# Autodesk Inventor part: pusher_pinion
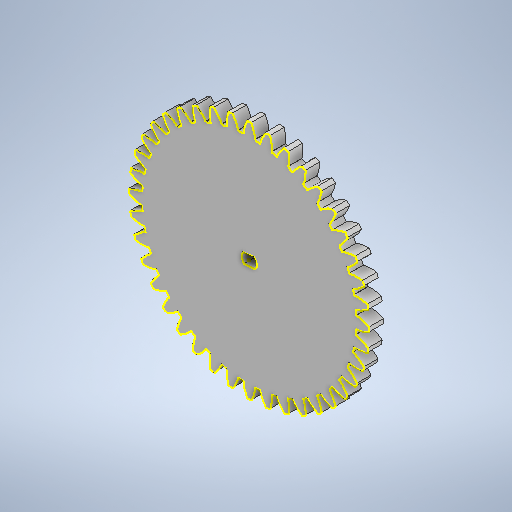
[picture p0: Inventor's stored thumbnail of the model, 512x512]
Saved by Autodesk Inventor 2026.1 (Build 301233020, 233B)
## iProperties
Company: meta-matic.com
Created: 2026-10
Part Number: pusher_pinion
Material: Generic
Description: Spur Gear - meta-matic-generator 1.3
Document SubType Name: Modeling
Designer: alolo
Authority: META-MATIC-ID: 1c046b0d7dfa
Density: 1 g/cm^3
Appearance: Default
Sending System: Open CASCADE
Preprocessor: meta-matic-generator 1.3
Title: Spur Gear_1c046b0d7dfa
Author: Takahashi Mizuki @tkhsmz
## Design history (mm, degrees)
feature "Base1"
sketch "Sketch1"
  geometry: L1 (-41.744, 1.365)-(-37.899, 1.365); L2 (-41.744, -2.135)-(-37.899, -2.135); A1 r 2.6 centre (-39.822, -0.385) between (-41.744, 1.365) and (-37.899, 1.365); 3 further points
  constraints: 4 end point, 4 point on circle, 2 midpoint, 1 centre point, 1 coincident, 1 horizontal, 1 parallel
  dimensions: "d0" = 5.2 diameter of A1; "d6" = 1.75 distance of point (-39.822, -0.385) point (-39.822, 1.365); "d7" = 1.75 distance of point (-39.822, -2.135) point (-39.822, -0.385) (= d6)
extrude "Extrusion1" cut sketch "Sketch1" stored distance "d1" = 10; taper "d2" = 0 deg
sketch "Sketch2"
  geometry: L1 (-2.379, -2.46)-(-2.292, -2.465) reference; L2 (-2.235, -0.635)-(-2.322, -0.634) reference; L3 (-2.515, 3.423)-(-2.428, 3.431) reference; L4 (-2.658, 5.248)-(-2.745, 5.235) reference; L5 (-3.57, 9.212)-(-3.485, 9.234) reference; L6 (-3.997, 10.993)-(-4.081, 10.966) reference; L7 (-5.518, 14.764)-(-5.438, 14.8) reference; L8 (-6.218, 16.457)-(-6.296, 16.418) reference; L9 (-8.31, 19.944)-(-8.236, 19.992) reference; L10 (-9.266, 21.506)-(-9.338, 21.455) reference; L11 (-11.878, 24.624)-(-11.813, 24.682) reference; L12 (-13.067, 26.017)-(-13.129, 25.955) reference; L13 (-16.134, 28.687)-(-16.079, 28.755) reference; L14 (-17.526, 29.877)-(-17.578, 29.806) reference; L15 (-20.974, 32.035)-(-20.93, 32.11) reference; L16 (-22.535, 32.992)-(-22.575, 32.914) reference; L17 (-26.277, 34.584)-(-26.246, 34.666) reference; L18 (-27.969, 35.285)-(-27.997, 35.202) reference; L19 (-31.914, 36.272)-(-31.896, 36.358) reference; L20 (-33.695, 36.7)-(-33.709, 36.614) reference; L21 (-37.746, 37.058)-(-37.741, 37.145) reference; L22 (-39.572, 37.202)-(-39.572, 37.115) reference; L23 (-43.629, 36.922)-(-43.638, 37.009) reference; L24 (-45.455, 36.779)-(-45.442, 36.692) reference; L25 (-49.418, 35.867)-(-49.44, 35.951) reference; L26 (-51.199, 35.44)-(-51.172, 35.356) reference; L27 (-54.971, 33.919)-(-55.006, 33.999) reference; L28 (-56.663, 33.219)-(-56.624, 33.141) reference; L29 (-60.151, 31.127)-(-60.198, 31.201) reference; L30 (-61.712, 30.171)-(-61.661, 30.099) reference; L31 (-64.83, 27.559)-(-64.888, 27.624) reference; L32 (-66.223, 26.37)-(-66.161, 26.308) reference; L33 (-68.893, 23.303)-(-68.961, 23.358) reference; L34 (-70.083, 21.911)-(-70.013, 21.858) reference; L35 (-72.241, 18.463)-(-72.317, 18.507) reference; L36 (-73.198, 16.902)-(-73.12, 16.862) reference; L37 (-74.79, 13.16)-(-74.872, 13.191) reference; L38 (-75.492, 11.468)-(-75.408, 11.44) reference; L39 (-76.478, 7.523)-(-76.564, 7.541) reference; L40 (-76.907, 5.742)-(-76.82, 5.728) reference; L41 (-77.264, 1.691)-(-77.352, 1.696) reference; L42 (-77.408, -0.135)-(-77.321, -0.135) reference; L43 (-77.128, -4.192)-(-77.215, -4.201) reference; L44 (-76.985, -6.018)-(-76.898, -6.005) reference; L45 (-76.073, -9.981)-(-76.158, -10.003) reference; L46 (-75.646, -11.762)-(-75.562, -11.735) reference; L47 (-74.125, -15.534)-(-74.206, -15.569) reference; L48 (-73.425, -17.226)-(-73.347, -17.187) reference; L49 (-71.333, -20.714)-(-71.407, -20.761) reference; L50 (-70.377, -22.276)-(-70.306, -22.224) reference; L51 (-67.765, -25.393)-(-67.831, -25.451) reference; L52 (-66.576, -26.786)-(-66.514, -26.724) reference; L53 (-63.509, -29.456)-(-63.564, -29.524) reference; L54 (-62.117, -30.646)-(-62.065, -30.576) reference; L55 (-58.67, -32.804)-(-58.714, -32.88) reference; L56 (-57.108, -33.761)-(-57.068, -33.683) reference; L57 (-53.366, -35.353)-(-53.398, -35.435) reference; L58 (-51.674, -36.055)-(-51.647, -35.971) reference; L59 (-47.729, -37.041)-(-47.747, -37.127) reference; L60 (-45.948, -37.47)-(-45.934, -37.383) reference; L61 (-41.897, -37.827)-(-41.902, -37.915) reference; L62 (-40.071, -37.972)-(-40.071, -37.884) reference; L63 (-36.014, -37.691)-(-36.005, -37.778) reference; L64 (-34.189, -37.548)-(-34.202, -37.461) reference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; A1 r 2.6 centre (-39.822, -0.385) between (-37.899, -2.135) and (-37.899, 1.365) reference; A2 r 37.5 centre (-39.822, -0.385) between (-2.379, -2.46) and (-2.322, -0.634) reference; A3 r 42 centre (-39.822, -0.385) between (2.16, 0.851) and (2.088, 2.37) reference; A4 r 37.5 centre (-39.822, -0.385) between (-2.515, 3.423) and (-2.745, 5.235) reference; A5 r 42 centre (-39.822, -0.385) between (1.45, 7.403) and (1.141, 8.892) reference; A6 r 37.5 centre (-39.822, -0.385) between (-3.57, 9.212) and (-4.081, 10.966) reference; A7 r 42 centre (-39.822, -0.385) between (-0.276, 13.763) and (-0.815, 15.186) reference; A8 r 37.5 centre (-39.822, -0.385) between (-5.518, 14.764) and (-6.296, 16.418) reference; A9 r 42 centre (-39.822, -0.385) between (-2.976, 19.775) and (-3.731, 21.096) reference; A10 r 37.5 centre (-39.822, -0.385) between (-8.31, 19.944) and (-9.338, 21.455) reference; A11 r 42 centre (-39.822, -0.385) between (-6.584, 25.291) and (-7.535, 26.478) reference; A12 r 37.5 centre (-39.822, -0.385) between (-11.878, 24.624) and (-13.129, 25.955) reference; A13 r 42 centre (-39.822, -0.385) between (-11.009, 30.174) and (-12.135, 31.198) reference; A14 r 37.5 centre (-39.822, -0.385) between (-16.134, 28.687) and (-17.578, 29.806) reference; A15 r 42 centre (-39.822, -0.385) between (-16.145, 34.305) and (-17.416, 35.14) reference; A16 r 37.5 centre (-39.822, -0.385) between (-20.974, 32.035) and (-22.575, 32.914) reference; A17 r 42 centre (-39.822, -0.385) between (-21.863, 37.582) and (-23.25, 38.208) reference; A18 r 37.5 centre (-39.822, -0.385) between (-26.277, 34.584) and (-27.997, 35.202) reference; A19 r 42 centre (-39.822, -0.385) between (-28.023, 39.924) and (-29.491, 40.325) reference; A20 r 37.5 centre (-39.822, -0.385) between (-31.914, 36.272) and (-33.709, 36.614) reference; A21 r 42 centre (-39.822, -0.385) between (-34.474, 41.274) and (-35.986, 41.44) reference; A22 r 37.5 centre (-39.822, -0.385) between (-37.746, 37.058) and (-39.572, 37.115) reference; A23 r 42 centre (-39.822, -0.385) between (-41.057, 41.597) and (-42.576, 41.525) reference; A24 r 37.5 centre (-39.822, -0.385) between (-43.629, 36.922) and (-45.442, 36.692) reference; A25 r 42 centre (-39.822, -0.385) between (-47.609, 40.887) and (-49.099, 40.578) reference; A26 r 37.5 centre (-39.822, -0.385) between (-49.418, 35.867) and (-51.172, 35.356) reference; A27 r 42 centre (-39.822, -0.385) between (-53.97, 39.161) and (-55.392, 38.622) reference; A28 r 37.5 centre (-39.822, -0.385) between (-54.971, 33.919) and (-56.624, 33.141) reference; A29 r 42 centre (-39.822, -0.385) between (-59.982, 36.461) and (-61.303, 35.706) reference; A30 r 37.5 centre (-39.822, -0.385) between (-60.151, 31.127) and (-61.661, 30.099) reference; A31 r 42 centre (-39.822, -0.385) between (-65.497, 32.853) and (-66.684, 31.902) reference; A32 r 37.5 centre (-39.822, -0.385) between (-64.83, 27.559) and (-66.161, 26.308) reference; A33 r 42 centre (-39.822, -0.385) between (-70.381, 28.428) and (-71.404, 27.302) reference; A34 r 37.5 centre (-39.822, -0.385) between (-68.893, 23.303) and (-70.013, 21.858) reference; A35 r 42 centre (-39.822, -0.385) between (-74.512, 23.292) and (-75.346, 22.02) reference; A36 r 37.5 centre (-39.822, -0.385) between (-72.241, 18.463) and (-73.12, 16.862) reference; A37 r 42 centre (-39.822, -0.385) between (-77.788, 17.574) and (-78.414, 16.187) reference; A38 r 37.5 centre (-39.822, -0.385) between (-74.79, 13.16) and (-75.408, 11.44) reference; A39 r 42 centre (-39.822, -0.385) between (-80.13, 11.414) and (-80.531, 9.946) reference; A40 r 37.5 centre (-39.822, -0.385) between (-76.478, 7.523) and (-76.82, 5.728) reference; A41 r 42 centre (-39.822, -0.385) between (-81.48, 4.963) and (-81.646, 3.451) reference; A42 r 37.5 centre (-39.822, -0.385) between (-77.264, 1.691) and (-77.321, -0.135) reference; A43 r 42 centre (-39.822, -0.385) between (-81.803, -1.62) and (-81.731, -3.139) reference; A44 r 37.5 centre (-39.822, -0.385) between (-77.128, -4.192) and (-76.898, -6.005) reference; A45 r 42 centre (-39.822, -0.385) between (-81.093, -8.172) and (-80.784, -9.662) reference; A46 r 37.5 centre (-39.822, -0.385) between (-76.073, -9.981) and (-75.562, -11.735) reference; A47 r 42 centre (-39.822, -0.385) between (-79.367, -14.533) and (-78.829, -15.955) reference; A48 r 37.5 centre (-39.822, -0.385) between (-74.125, -15.534) and (-73.347, -17.187) reference; A49 r 42 centre (-39.822, -0.385) between (-76.667, -20.545) and (-75.913, -21.866) reference; A50 r 37.5 centre (-39.822, -0.385) between (-71.333, -20.714) and (-70.306, -22.224) reference; A51 r 42 centre (-39.822, -0.385) between (-73.06, -26.06) and (-72.108, -27.247) reference; A52 r 37.5 centre (-39.822, -0.385) between (-67.765, -25.393) and (-66.514, -26.724) reference; A53 r 42 centre (-39.822, -0.385) between (-68.634, -30.944) and (-67.508, -31.967) reference; A54 r 37.5 centre (-39.822, -0.385) between (-63.509, -29.456) and (-62.065, -30.576) reference; A55 r 42 centre (-39.822, -0.385) between (-63.499, -35.075) and (-62.227, -35.909) reference; A56 r 37.5 centre (-39.822, -0.385) between (-58.67, -32.804) and (-57.068, -33.683) reference; A57 r 42 centre (-39.822, -0.385) between (-57.78, -38.352) and (-56.394, -38.977) reference; A58 r 37.5 centre (-39.822, -0.385) between (-53.366, -35.353) and (-51.647, -35.971) reference; A59 r 42 centre (-39.822, -0.385) between (-51.62, -40.693) and (-50.152, -41.094) reference; A60 r 37.5 centre (-39.822, -0.385) between (-47.729, -37.041) and (-45.934, -37.383) reference; A61 r 42 centre (-39.822, -0.385) between (-45.169, -42.043) and (-43.657, -42.209) reference; A62 r 37.5 centre (-39.822, -0.385) between (-41.897, -37.827) and (-40.071, -37.884) reference; A63 r 42 centre (-39.822, -0.385) between (-38.586, -42.366) and (-37.067, -42.294) reference; A64 r 37.5 centre (-39.822, -0.385) between (-36.014, -37.691) and (-34.202, -37.461) reference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; 1 further point
  constraints: 80 other
extrude "Extrusion2" cut sketch "Sketch2" distance "d3" = 5; taper "d4" = 0 deg
sketch "Sketch3"
  geometry: L1 (-41.744, -2.135)-(-37.899, -2.135) reference; L2 (-37.899, 1.365)-(-41.744, 1.365) reference; L3 (-2.515, 3.423)-(-2.428, 3.431) reference; L4 (-2.658, 5.248)-(-2.745, 5.235) reference; L5 (-3.57, 9.212)-(-3.485, 9.234) reference; L6 (-3.997, 10.993)-(-4.081, 10.966) reference; L7 (-5.518, 14.764)-(-5.438, 14.8) reference; L8 (-6.218, 16.457)-(-6.296, 16.418) reference; L9 (-8.31, 19.944)-(-8.236, 19.992) reference; L10 (-9.266, 21.506)-(-9.338, 21.455) reference; L11 (-11.878, 24.624)-(-11.813, 24.682) reference; L12 (-13.067, 26.017)-(-13.129, 25.955) reference; L13 (-16.134, 28.687)-(-16.079, 28.755) reference; L14 (-17.526, 29.877)-(-17.578, 29.806) reference; L15 (-20.974, 32.035)-(-20.93, 32.11) reference; L16 (-22.535, 32.992)-(-22.575, 32.914) reference; L17 (-26.277, 34.584)-(-26.246, 34.666) reference; L18 (-27.969, 35.285)-(-27.997, 35.202) reference; L19 (-31.914, 36.272)-(-31.896, 36.358) reference; L20 (-33.695, 36.7)-(-33.709, 36.614) reference; L21 (-37.746, 37.058)-(-37.741, 37.145) reference; L22 (-39.572, 37.202)-(-39.572, 37.115) reference; L23 (-43.629, 36.922)-(-43.638, 37.009) reference; L24 (-45.455, 36.779)-(-45.442, 36.692) reference; L25 (-49.418, 35.867)-(-49.44, 35.951) reference; L26 (-51.199, 35.44)-(-51.172, 35.356) reference; L27 (-54.971, 33.919)-(-55.006, 33.999) reference; L28 (-56.663, 33.219)-(-56.624, 33.141) reference; L29 (-60.151, 31.127)-(-60.198, 31.201) reference; L30 (-61.712, 30.171)-(-61.661, 30.099) reference; L31 (-64.83, 27.559)-(-64.888, 27.624) reference; L32 (-66.223, 26.37)-(-66.161, 26.308) reference; L33 (-68.893, 23.303)-(-68.961, 23.358) reference; L34 (-70.083, 21.911)-(-70.013, 21.858) reference; L35 (-72.241, 18.463)-(-72.317, 18.507) reference; L36 (-73.198, 16.902)-(-73.12, 16.862) reference; L37 (-74.79, 13.16)-(-74.872, 13.191) reference; L38 (-75.492, 11.468)-(-75.408, 11.44) reference; L39 (-76.478, 7.523)-(-76.564, 7.541) reference; L40 (-76.907, 5.742)-(-76.82, 5.728) reference; L41 (-77.264, 1.691)-(-77.352, 1.696) reference; L42 (-77.408, -0.135)-(-77.321, -0.135) reference; L43 (-77.128, -4.192)-(-77.215, -4.201) reference; L44 (-76.985, -6.018)-(-76.898, -6.005) reference; L45 (-76.073, -9.981)-(-76.158, -10.003) reference; L46 (-75.646, -11.762)-(-75.562, -11.735) reference; L47 (-74.125, -15.534)-(-74.206, -15.569) reference; L48 (-73.425, -17.226)-(-73.347, -17.187) reference; L49 (-71.333, -20.714)-(-71.407, -20.761) reference; L50 (-70.377, -22.276)-(-70.306, -22.224) reference; L51 (-67.765, -25.393)-(-67.831, -25.451) reference; L52 (-66.576, -26.786)-(-66.514, -26.724) reference; L53 (-63.509, -29.456)-(-63.564, -29.524) reference; L54 (-62.117, -30.646)-(-62.065, -30.576) reference; L55 (-58.67, -32.804)-(-58.714, -32.88) reference; L56 (-57.108, -33.761)-(-57.068, -33.683) reference; L57 (-53.366, -35.353)-(-53.398, -35.435) reference; L58 (-51.674, -36.055)-(-51.647, -35.971) reference; L59 (-47.729, -37.041)-(-47.747, -37.127) reference; L60 (-45.948, -37.47)-(-45.934, -37.383) reference; L61 (-41.897, -37.827)-(-41.902, -37.915) reference; L62 (-40.071, -37.972)-(-40.071, -37.884) reference; L63 (-36.014, -37.691)-(-36.005, -37.778) reference; L64 (-34.189, -37.548)-(-34.202, -37.461) reference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; A1 r 2.6 centre (-39.822, -0.385) between (-41.744, 1.365) and (-41.744, -2.135) reference; A2 r 2.6 centre (-39.822, -0.385) between (-37.899, -2.135) and (-37.899, 1.365) reference; A3 r 37.5 centre (-39.822, -0.385) between (-2.515, 3.423) and (-2.745, 5.235) reference; A4 r 42 centre (-39.822, -0.385) between (1.45, 7.403) and (1.141, 8.892) reference; A5 r 37.5 centre (-39.822, -0.385) between (-3.57, 9.212) and (-4.081, 10.966) reference; A6 r 42 centre (-39.822, -0.385) between (-0.276, 13.763) and (-0.815, 15.186) reference; A7 r 37.5 centre (-39.822, -0.385) between (-5.518, 14.764) and (-6.296, 16.418) reference; A8 r 42 centre (-39.822, -0.385) between (-2.976, 19.775) and (-3.731, 21.096) reference; A9 r 37.5 centre (-39.822, -0.385) between (-8.31, 19.944) and (-9.338, 21.455) reference; A10 r 42 centre (-39.822, -0.385) between (-6.584, 25.291) and (-7.535, 26.478) reference; A11 r 37.5 centre (-39.822, -0.385) between (-11.878, 24.624) and (-13.129, 25.955) reference; A12 r 42 centre (-39.822, -0.385) between (-11.009, 30.174) and (-12.135, 31.198) reference; A13 r 37.5 centre (-39.822, -0.385) between (-16.134, 28.687) and (-17.578, 29.806) reference; A14 r 42 centre (-39.822, -0.385) between (-16.145, 34.305) and (-17.416, 35.14) reference; A15 r 37.5 centre (-39.822, -0.385) between (-20.974, 32.035) and (-22.575, 32.914) reference; A16 r 42 centre (-39.822, -0.385) between (-21.863, 37.582) and (-23.25, 38.208) reference; A17 r 37.5 centre (-39.822, -0.385) between (-26.277, 34.584) and (-27.997, 35.202) reference; A18 r 42 centre (-39.822, -0.385) between (-28.023, 39.924) and (-29.491, 40.325) reference; A19 r 37.5 centre (-39.822, -0.385) between (-31.914, 36.272) and (-33.709, 36.614) reference; A20 r 42 centre (-39.822, -0.385) between (-34.474, 41.274) and (-35.986, 41.44) reference; A21 r 37.5 centre (-39.822, -0.385) between (-37.746, 37.058) and (-39.572, 37.115) reference; A22 r 42 centre (-39.822, -0.385) between (-41.057, 41.597) and (-42.576, 41.525) reference; A23 r 37.5 centre (-39.822, -0.385) between (-43.629, 36.922) and (-45.442, 36.692) reference; A24 r 42 centre (-39.822, -0.385) between (-47.609, 40.887) and (-49.099, 40.578) reference; A25 r 37.5 centre (-39.822, -0.385) between (-49.418, 35.867) and (-51.172, 35.356) reference; A26 r 42 centre (-39.822, -0.385) between (-53.97, 39.161) and (-55.392, 38.622) reference; A27 r 37.5 centre (-39.822, -0.385) between (-54.971, 33.919) and (-56.624, 33.141) reference; A28 r 42 centre (-39.822, -0.385) between (-59.982, 36.461) and (-61.303, 35.706) reference; A29 r 37.5 centre (-39.822, -0.385) between (-60.151, 31.127) and (-61.661, 30.099) reference; A30 r 42 centre (-39.822, -0.385) between (-65.497, 32.853) and (-66.684, 31.902) reference; A31 r 37.5 centre (-39.822, -0.385) between (-64.83, 27.559) and (-66.161, 26.308) reference; A32 r 42 centre (-39.822, -0.385) between (-70.381, 28.428) and (-71.404, 27.302) reference; A33 r 37.5 centre (-39.822, -0.385) between (-68.893, 23.303) and (-70.013, 21.858) reference; A34 r 42 centre (-39.822, -0.385) between (-74.512, 23.292) and (-75.346, 22.02) reference; A35 r 37.5 centre (-39.822, -0.385) between (-72.241, 18.463) and (-73.12, 16.862) reference; A36 r 42 centre (-39.822, -0.385) between (-77.788, 17.574) and (-78.414, 16.187) reference; A37 r 37.5 centre (-39.822, -0.385) between (-74.79, 13.16) and (-75.408, 11.44) reference; A38 r 42 centre (-39.822, -0.385) between (-80.13, 11.414) and (-80.531, 9.946) reference; A39 r 37.5 centre (-39.822, -0.385) between (-76.478, 7.523) and (-76.82, 5.728) reference; A40 r 42 centre (-39.822, -0.385) between (-81.48, 4.963) and (-81.646, 3.451) reference; A41 r 37.5 centre (-39.822, -0.385) between (-77.264, 1.691) and (-77.321, -0.135) reference; A42 r 42 centre (-39.822, -0.385) between (-81.803, -1.62) and (-81.731, -3.139) reference; A43 r 37.5 centre (-39.822, -0.385) between (-77.128, -4.192) and (-76.898, -6.005) reference; A44 r 42 centre (-39.822, -0.385) between (-81.093, -8.172) and (-80.784, -9.662) reference; A45 r 37.5 centre (-39.822, -0.385) between (-76.073, -9.981) and (-75.562, -11.735) reference; A46 r 42 centre (-39.822, -0.385) between (-79.367, -14.533) and (-78.829, -15.955) reference; A47 r 37.5 centre (-39.822, -0.385) between (-74.125, -15.534) and (-73.347, -17.187) reference; A48 r 42 centre (-39.822, -0.385) between (-76.667, -20.545) and (-75.913, -21.866) reference; A49 r 37.5 centre (-39.822, -0.385) between (-71.333, -20.714) and (-70.306, -22.224) reference; A50 r 42 centre (-39.822, -0.385) between (-73.06, -26.06) and (-72.108, -27.247) reference; A51 r 37.5 centre (-39.822, -0.385) between (-67.765, -25.393) and (-66.514, -26.724) reference; A52 r 42 centre (-39.822, -0.385) between (-68.634, -30.944) and (-67.508, -31.967) reference; A53 r 37.5 centre (-39.822, -0.385) between (-63.509, -29.456) and (-62.065, -30.576) reference; A54 r 42 centre (-39.822, -0.385) between (-63.499, -35.075) and (-62.227, -35.909) reference; A55 r 37.5 centre (-39.822, -0.385) between (-58.67, -32.804) and (-57.068, -33.683) reference; A56 r 42 centre (-39.822, -0.385) between (-57.78, -38.352) and (-56.394, -38.977) reference; A57 r 37.5 centre (-39.822, -0.385) between (-53.366, -35.353) and (-51.647, -35.971) reference; A58 r 42 centre (-39.822, -0.385) between (-51.62, -40.693) and (-50.152, -41.094) reference; A59 r 37.5 centre (-39.822, -0.385) between (-47.729, -37.041) and (-45.934, -37.383) reference; A60 r 42 centre (-39.822, -0.385) between (-45.169, -42.043) and (-43.657, -42.209) reference; A61 r 37.5 centre (-39.822, -0.385) between (-41.897, -37.827) and (-40.071, -37.884) reference; A62 r 42 centre (-39.822, -0.385) between (-38.586, -42.366) and (-37.067, -42.294) reference; A63 r 37.5 centre (-39.822, -0.385) between (-36.014, -37.691) and (-34.202, -37.461) reference; A64 r 42 centre (-39.822, -0.385) between (-32.034, -41.656) and (-30.545, -41.347) reference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; 1 further point
  constraints: 80 other
  node "Projected Loop2"
body "Solid1"
node "Projected Loop1"
